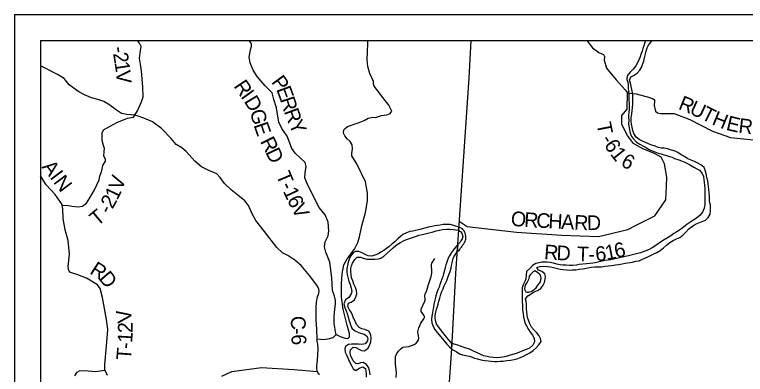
# Model space of a CAD drawing. Extents: x -84548 to 2262448, y -162180 to 525962.
# Drawn here: x -37475 to -22558, y 159669 to 167016 of the extents above; entities that cross this region are included whole.
import ezdxf

# ---------------------------------------------------------------- set-up
doc = ezdxf.new("R2010")
doc.units = 0
for name, color, linetype in [('GM_X_County', 7, 'Continuous'), ('GM_X_County_Road', 7, 'Continuous'), ('GM_X_Interstate_Location', 7, 'Continuous'), ('GM_X_Major_Lake', 7, 'Continuous'), ('GM_X_Minor_Lake', 7, 'Continuous'), ('GM_X_Minor_River_Text', 7, 'Continuous'), ('GM_X_Township_Road', 7, 'Continuous'), ('GM_X_Township_Road_Text', 7, 'Continuous')]:
    doc.layers.add(name, color=color, linetype=linetype)

msp = doc.modelspace()

# ---------------------------------------------------------------- linework, layer by layer
at = {"layer": 'GM_X_County'}
for p, q in [((-37475, 167016), (-515, 167016)), ((-37475, 167016), (-37475, 130056)), ((-36947, 166488), (-36947, 130584)), ((-36947, 166488), (-1043, 166488)), ((-36947, 166488), (-36947, 130584)), ((-36947, 166488), (-1043, 166488))]:
    msp.add_line(p, q, dxfattribs=at)
at = {"layer": 'GM_X_Interstate_Location'}
for p, q in [((-28406, 162678), (-28411, 162615)), ((-28411, 162615), (-28406, 162678)), ((-28430, 162322), (-28440, 162173)), ((-28440, 162173), (-28430, 162322)), ((-28547, 160299), (-28554, 160184)), ((-28554, 160184), (-28547, 160299))]:
    msp.add_line(p, q, dxfattribs=at)
for points in [[(-24599, 166488), (-24619, 166428), (-24633, 166378), (-24651, 166326), (-24665, 166270), (-24683, 166220), (-24706, 166156), (-24728, 166106), (-24758, 166034), (-24794, 165971), (-24846, 165899), (-24914, 165835), (-24973, 165765), (-24979, 165693), (-24957, 165639), (-24953, 165587), (-24951, 165519), (-24945, 165450), (-24937, 165384), (-24934, 165332), (-24934, 165266), (-24932, 165200), (-24932, 165092), (-24940, 165014), (-24946, 164964), (-24944, 164914), (-24939, 164862), (-24941, 164788), (-24937, 164738), (-24923, 164668), (-24907, 164598), (-24883, 164530), (-24845, 164478), (-24779, 164410), (-24712, 164368), (-24640, 164328), (-24578, 164292), (-24522, 164263), (-24464, 164237), (-24408, 164215), (-24340, 164189), (-24278, 164173), (-24218, 164149), (-24166, 164136), (-24108, 164120), (-24054, 164104), (-24002, 164080), (-23918, 164052), (-23860, 164030), (-23796, 164000), (-23742, 163973), (-23676, 163939)], [(-23402, 163897), (-23464, 163947), (-23530, 163983), (-23594, 164013), (-23734, 164073), (-23799, 164115), (-23867, 164154), (-23937, 164202), (-23989, 164224), (-24063, 164250), (-24145, 164276), (-24215, 164288), (-24277, 164289), (-24337, 164299), (-24401, 164327), (-24469, 164351), (-24537, 164379), (-24609, 164411), (-24659, 164432), (-24725, 164468), (-24787, 164516), (-24833, 164586), (-24857, 164648), (-24867, 164716), (-24883, 164780), (-24889, 164848), (-24888, 164910), (-24878, 164990), (-24870, 165048), (-24860, 165118), (-24858, 165178), (-24854, 165235), (-24852, 165289), (-24857, 165357), (-24863, 165425), (-24887, 165545), (-24905, 165613), (-24925, 165679), (-24893, 165745), (-24829, 165781), (-24768, 165817), (-24710, 165882), (-24674, 165950), (-24656, 166000), (-24634, 166068), (-24614, 166130), (-24581, 166266), (-24563, 166336), (-24533, 166394), (-24483, 166461), (-24454, 166488)], [(-23676, 163939), (-23608, 163903), (-23546, 163869), (-23496, 163837), (-23440, 163769), (-23416, 163709), (-23404, 163641), (-23400, 163591), (-23393, 163527), (-23387, 163455), (-23385, 163397), (-23383, 163325), (-23383, 163137), (-23396, 163061), (-23426, 162993), (-23482, 162922), (-23556, 162856), (-23612, 162822), (-23750, 162730), (-23817, 162681), (-23883, 162629), (-23955, 162583), (-24017, 162543), (-24077, 162496), (-24137, 162462), (-24215, 162414), (-24288, 162368), (-24340, 162332), (-24406, 162287), (-24458, 162255), (-24536, 162215), (-24590, 162191), (-24644, 162173), (-24696, 162148), (-24756, 162138), (-24810, 162126), (-24887, 162104), (-24945, 162092), (-25009, 162077), (-25065, 162065), (-25125, 162049), (-25181, 162037), (-25245, 162023), (-25305, 162011), (-25357, 162004), (-25425, 161994), (-25483, 161980), (-25567, 161960), (-25623, 161948), (-25675, 161939), (-25731, 161931), (-25802, 161925), (-25876, 161917), (-25956, 161913), (-26008, 161900), (-26080, 161896), (-26146, 161896), (-26216, 161898), (-26284, 161902), (-26338, 161907), (-26406, 161923), (-26476, 161939), (-26544, 161955), (-26612, 161961), (-26716, 161960), (-26770, 161950), (-26838, 161934), (-26906, 161890), (-26961, 161830), (-27025, 161769), (-27033, 161695), (-27041, 161623), (-27057, 161569), (-27095, 161501), (-27113, 161435), (-27116, 161369), (-27114, 161319), (-27114, 161205), (-27112, 161145), (-27108, 161095), (-27108, 161045), (-27106, 160995), (-27095, 160906), (-27087, 160846), (-27073, 160782), (-27051, 160710), (-27027, 160658), (-26983, 160587), (-26953, 160533), (-26905, 160469), (-26868, 160407), (-26860, 160333), (-26896, 160266), (-26966, 160208), (-27032, 160178), (-27084, 160154), (-27214, 160103), (-27285, 160083), (-27361, 160059), (-27441, 160037), (-27507, 160023)], [(-27147, 160014), (-27089, 160040), (-27026, 160072), (-26956, 160112), (-26890, 160158), (-26826, 160211), (-26772, 160273), (-26728, 160341), (-26739, 160399), (-26765, 160455), (-26817, 160521), (-26867, 160569), (-26921, 160633), (-26959, 160703), (-26979, 160757), (-27003, 160831), (-27011, 160887), (-27020, 160949), (-27024, 160999), (-27024, 161105), (-27034, 161161), (-27044, 161213), (-26996, 161273), (-26932, 161317), (-26869, 161353), (-26801, 161382), (-26735, 161426), (-26683, 161494), (-26659, 161544), (-26643, 161612), (-26639, 161666), (-26653, 161722), (-26716, 161772), (-26784, 161794), (-26818, 161850), (-26754, 161872), (-26678, 161878), (-26600, 161873), (-26534, 161865), (-26472, 161853), (-26340, 161821), (-26276, 161810), (-26212, 161804), (-26154, 161798), (-26098, 161802), (-26020, 161806), (-25950, 161821), (-25892, 161827), (-25840, 161833), (-25776, 161847), (-25704, 161857), (-25636, 161863), (-25566, 161866), (-25495, 161868), (-25427, 161876), (-25357, 161886), (-25291, 161892), (-25211, 161905), (-25141, 161915), (-25071, 161927), (-25015, 161939), (-24863, 161964), (-24793, 161978), (-24725, 161990), (-24671, 162018), (-24597, 162051), (-24546, 162073), (-24438, 162121), (-24364, 162157), (-24296, 162202), (-24232, 162254), (-24168, 162310), (-24101, 162360), (-24029, 162404), (-23967, 162437), (-23899, 162465), (-23831, 162517), (-23771, 162573), (-23715, 162638), (-23640, 162698), (-23578, 162736), (-23508, 162766), (-23442, 162790), (-23372, 162819), (-23316, 162875), (-23280, 162943), (-23268, 163011), (-23267, 163061), (-23273, 163127), (-23289, 163201), (-23291, 163269), (-23293, 163319), (-23299, 163373), (-23301, 163453), (-23308, 163507), (-23316, 163561), (-23326, 163619), (-23342, 163687), (-23356, 163765), (-23376, 163837), (-23402, 163897)], [(-28406, 162678), (-28511, 162710), (-28585, 162731), (-28650, 162733), (-28726, 162729), (-28790, 162719), (-28840, 162711), (-28898, 162701), (-28960, 162689), (-29029, 162673), (-29099, 162653), (-29177, 162635), (-29231, 162623), (-29293, 162607), (-29349, 162597), (-29406, 162585), (-29474, 162561), (-29548, 162525), (-29600, 162487), (-29650, 162439), (-29715, 162373), (-29767, 162333), (-29835, 162277), (-29885, 162237), (-29939, 162199), (-29996, 162163), (-30046, 162133), (-30120, 162101), (-30184, 162085), (-30258, 162091), (-30320, 162117), (-30382, 162151), (-30445, 162177), (-30517, 162179), (-30567, 162149), (-30621, 162085), (-30647, 162025), (-30667, 161959), (-30682, 161893), (-30690, 161829), (-30696, 161764), (-30688, 161712), (-30654, 161576), (-30628, 161502), (-30604, 161432), (-30594, 161362), (-30606, 161312), (-30654, 161240), (-30722, 161192), (-30755, 161109), (-30733, 161035), (-30705, 160969), (-30685, 160911), (-30667, 160845), (-30649, 160785), (-30633, 160729), (-30617, 160679), (-30589, 160611), (-30537, 160568), (-30484, 160538), (-30414, 160512), (-30342, 160488), (-30292, 160458), (-30266, 160408), (-30270, 160352), (-30316, 160290), (-30389, 160278), (-30457, 160284), (-30525, 160286), (-30589, 160286), (-30657, 160278), (-30719, 160242), (-30733, 160192), (-30725, 160124), (-30695, 160056), (-30657, 159972), (-30623, 159901), (-30589, 159835), (-30563, 159783), (-30507, 159749), (-30439, 159797), (-30367, 159823), (-30313, 159791), (-30303, 159735), (-30301, 159681), (-30301, 159611)], [(-30217, 159659), (-30221, 159717), (-30247, 159803), (-30291, 159871), (-30361, 159911), (-30411, 159907), (-30461, 159887), (-30511, 159889), (-30565, 159947), (-30593, 160006), (-30615, 160056), (-30625, 160124), (-30621, 160174), (-30561, 160222), (-30509, 160216), (-30445, 160184), (-30391, 160158), (-30339, 160150), (-30262, 160196), (-30230, 160256), (-30204, 160336), (-30196, 160412), (-30206, 160478), (-30246, 160554), (-30324, 160586), (-30390, 160602), (-30442, 160628), (-30496, 160687), (-30526, 160753), (-30554, 160819), (-30580, 160881), (-30604, 160937), (-30638, 160989), (-30676, 161057), (-30660, 161121), (-30608, 161143), (-30540, 161195), (-30510, 161254), (-30490, 161316), (-30494, 161380), (-30514, 161444), (-30548, 161512), (-30572, 161582), (-30596, 161642), (-30606, 161700), (-30611, 161770), (-30609, 161829), (-30601, 161885), (-30577, 161937), (-30529, 162015), (-30479, 162065), (-30415, 162061), (-30361, 162043), (-30288, 162023), (-30238, 162019), (-30180, 162019), (-30124, 162022), (-30050, 162028), (-30000, 162044), (-29939, 162084), (-29879, 162137), (-29811, 162199), (-29743, 162257), (-29669, 162319), (-29600, 162363), (-29526, 162405), (-29474, 162423), (-29414, 162445), (-29356, 162461), (-29271, 162495), (-29219, 162513), (-29155, 162529), (-29093, 162541), (-29015, 162559), (-28953, 162575), (-28868, 162599), (-28804, 162611), (-28738, 162628), (-28652, 162636), (-28592, 162636), (-28523, 162630), (-28411, 162615)], [(-28440, 162173), (-28389, 162222), (-28371, 162246), (-28355, 162266), (-28340, 162288), (-28322, 162314), (-28304, 162338), (-28290, 162362), (-28278, 162386), (-28270, 162410), (-28266, 162430), (-28264, 162452), (-28264, 162472), (-28266, 162494), (-28270, 162514), (-28273, 162536), (-28279, 162556), (-28291, 162578), (-28301, 162603), (-28323, 162629), (-28339, 162651), (-28406, 162678)], [(-28411, 162615), (-28365, 162577), (-28348, 162555), (-28338, 162531), (-28330, 162498), (-28328, 162478), (-28334, 162458), (-28342, 162436), (-28350, 162416), (-28366, 162394), (-28382, 162372), (-28430, 162322)], [(-28430, 162322), (-28500, 162236), (-28554, 162158), (-28598, 162090), (-28626, 162039), (-28654, 161961), (-28669, 161909), (-28685, 161853), (-28699, 161789), (-28719, 161725), (-28735, 161667), (-28753, 161611), (-28773, 161559), (-28793, 161503), (-28811, 161453), (-28834, 161395), (-28854, 161338), (-28876, 161270), (-28890, 161214), (-28904, 161156), (-28914, 161104), (-28926, 161038), (-28936, 160982), (-28946, 160928), (-28958, 160860), (-28962, 160798), (-28957, 160724), (-28937, 160669), (-28903, 160595), (-28850, 160527), (-28808, 160475), (-28744, 160405), (-28704, 160353), (-28654, 160283), (-28554, 160184)], [(-28547, 160299), (-28649, 160423), (-28758, 160561), (-28816, 160631), (-28860, 160697), (-28886, 160772), (-28892, 160822), (-28892, 160874), (-28878, 160940), (-28862, 161000), (-28840, 161056), (-28826, 161106), (-28814, 161166), (-28796, 161228), (-28782, 161278), (-28761, 161346), (-28729, 161419), (-28703, 161475), (-28679, 161533), (-28653, 161589), (-28629, 161649), (-28601, 161721), (-28581, 161771), (-28566, 161839), (-28556, 161895), (-28546, 161945), (-28528, 162017), (-28512, 162067), (-28440, 162173)], [(-26855, 161786), (-26899, 161758), (-26925, 161730), (-26945, 161708), (-26969, 161675), (-26979, 161637), (-26987, 161607), (-27011, 161555), (-27051, 161493), (-27061, 161457), (-27064, 161409), (-27036, 161353)], [(-27036, 161353), (-27010, 161347), (-26976, 161351), (-26958, 161355), (-26930, 161365), (-26897, 161383), (-26863, 161408), (-26831, 161434), (-26793, 161492), (-26761, 161532), (-26743, 161560), (-26731, 161604), (-26729, 161628), (-26743, 161698), (-26755, 161710), (-26799, 161750), (-26855, 161786)], [(-28317, 160227), (-28426, 160264), (-28547, 160299)], [(-27507, 160023), (-27573, 160016), (-27645, 160010), (-27709, 160012), (-27777, 160024), (-27829, 160032), (-27901, 160049), (-27971, 160079), (-28047, 160119), (-28119, 160153), (-28189, 160181), (-28259, 160207), (-28317, 160227)], [(-28554, 160184), (-28461, 160138)], [(-28461, 160138), (-28391, 160090), (-28329, 160066), (-28267, 160056), (-28199, 160043), (-28135, 160021), (-28085, 160001), (-28025, 159987), (-27957, 159969), (-27879, 159953), (-27807, 159944), (-27739, 159938), (-27677, 159934), (-27625, 159934), (-27561, 159936), (-27501, 159942), (-27427, 159951), (-27355, 159959), (-27275, 159975), (-27223, 159985), (-27147, 160014)]]:
    msp.add_lwpolyline(points, dxfattribs=at)
at = {"layer": 'GM_X_Major_Lake'}
for p, q in [((-28161, 166488), (-28206, 165718)), ((-28206, 165718), (-28474, 161726)), ((-28474, 161726), (-28557, 160201)), ((-28557, 160201), (-28663, 158686))]:
    msp.add_line(p, q, dxfattribs=at)
at = {"layer": 'GM_X_Minor_Lake'}
for points in [[(-35023, 164960), (-34967, 165052), (-34884, 165236), (-34850, 165340), (-34859, 165541), (-34882, 165863), (-34908, 166003), (-34927, 166129), (-34905, 166275), (-34892, 166361), (-34924, 166433), (-34963, 166488)], [(-31298, 160398), (-31160, 160384), (-31050, 160401), (-30974, 160425), (-30912, 160483), (-30920, 160505), (-30950, 160709), (-30953, 160853), (-30939, 160999), (-30922, 161100), (-30926, 161178), (-30946, 161264), (-30987, 161382), (-30991, 161528), (-30996, 161644), (-31043, 161962), (-31121, 162164), (-31148, 162274), (-31136, 162374), (-31076, 162498), (-31061, 162598), (-31073, 162780), (-31134, 162926), (-31261, 163076), (-31383, 163312), (-31510, 163578), (-31553, 163682), (-31545, 163784), (-31523, 163916), (-31544, 163994), (-31745, 164188), (-31815, 164281), (-31914, 164531), (-32018, 164693), (-32081, 164817), (-32132, 165111), (-32182, 165281), (-32217, 165421), (-32359, 165559), (-32522, 165751), (-32605, 165881), (-32665, 166034), (-32688, 166146), (-32658, 166293), (-32642, 166363), (-32640, 166411), (-32663, 166461), (-32687, 166488)], [(-30728, 164687), (-30678, 164733), (-30444, 164811), (-30340, 164852), (-30256, 164900), (-30170, 164920), (-30110, 164916), (-29984, 164954), (-29876, 164971), (-29806, 164993), (-29776, 165047), (-29839, 165167), (-29961, 165325), (-30090, 165495), (-30138, 165553), (-30148, 165603), (-30146, 165649), (-30221, 165811), (-30267, 165959), (-30280, 166089), (-30268, 166265), (-30263, 166411), (-30266, 166488)], [(-25795, 166488), (-25679, 166340), (-25549, 166242), (-25457, 166198), (-25445, 166189), (-25440, 166178), (-25436, 166159), (-25440, 166086), (-25392, 165925), (-25193, 165681), (-25013, 165480), (-24966, 165417), (-24790, 165396), (-24537, 165330), (-24441, 165294), (-24413, 165274), (-24411, 165248), (-24423, 165160), (-24393, 165044), (-24352, 165007), (-24291, 164994), (-24010, 164994), (-23695, 164872), (-23226, 164635), (-22865, 164505), (-22333, 164453)], [(-24169, 163504), (-24169, 163506), (-24162, 163696), (-24208, 163971), (-24280, 164103), (-24416, 164181), (-24667, 164280), (-24842, 164384), (-24966, 164550), (-25083, 164773), (-25079, 164955), (-24970, 165083), (-24966, 165417)], [(-30912, 160483), (-30826, 160443), (-30729, 160410), (-30675, 160404), (-30641, 160438), (-30638, 160502), (-30684, 160674), (-30769, 161004), (-30804, 161248), (-30805, 161520), (-30788, 161720), (-30752, 161908), (-30685, 162031), (-30539, 162223), (-30470, 162364), (-30432, 162476), (-30387, 162702), (-30314, 162976), (-30274, 163211), (-30269, 163373), (-30314, 163603), (-30479, 163955), (-30594, 164134), (-30594, 164178), (-30580, 164277), (-30584, 164355), (-30623, 164427), (-30687, 164482), (-30737, 164538), (-30761, 164592), (-30755, 164662), (-30735, 164681), (-30728, 164687)], [(-36501, 163120), (-36406, 163127), (-36302, 163105), (-36174, 163092), (-36086, 163106), (-36004, 163164), (-35940, 163272), (-35843, 163441), (-35751, 163639), (-35733, 163717), (-35706, 163791), (-35684, 163863), (-35674, 163933), (-35622, 164022), (-35618, 164062), (-35653, 164122), (-35647, 164220), (-35639, 164284), (-35661, 164344), (-35690, 164442), (-35686, 164547), (-35686, 164548)], [(-36375, 161822), (-36382, 161870), (-36357, 162121), (-36379, 162403), (-36442, 162621), (-36481, 162855), (-36492, 163051), (-36501, 163120), (-36507, 163136), (-36645, 163341), (-36831, 163542), (-36947, 163723)], [(-28402, 162796), (-28235, 162692), (-27229, 162572), (-26304, 162514), (-25554, 162485), (-24955, 162631), (-24877, 162670)], [(-35634, 159757), (-35634, 159868), (-35596, 160251), (-35575, 160584), (-35602, 160790), (-35681, 161236), (-35728, 161424), (-35786, 161498), (-36009, 161631), (-36187, 161705), (-36331, 161748), (-36371, 161790), (-36373, 161801), (-36375, 161822)], [(-33242, 159633), (-33041, 159731), (-32434, 159811), (-31774, 159766), (-31295, 159728)], [(-36248, 159637), (-36198, 159712), (-36147, 159744), (-36046, 159746), (-35824, 159730), (-35634, 159757), (-35586, 159655)]]:
    msp.add_lwpolyline(points, dxfattribs=at)
at = {"layer": 'GM_X_Minor_River_Text'}
msp.add_lwpolyline([(-31243, 159664), (-31262, 159676), (-31278, 159691), (-31288, 159709), (-31295, 159728), (-31303, 159780), (-31303, 159853), (-31294, 159954), (-31279, 160182), (-31287, 160284), (-31298, 160344), (-31298, 160398), (-31308, 160596), (-31317, 160774), (-31321, 160910), (-31322, 161026), (-31310, 161145), (-31289, 161255), (-31265, 161325), (-31260, 161373), (-31265, 161409), (-31287, 161459), (-31307, 161489), (-31454, 161691), (-31623, 161890), (-31757, 162002), (-31898, 162094), (-32006, 162152), (-32120, 162261), (-32376, 162585), (-32554, 162813), (-32635, 162962), (-32702, 163116), (-32772, 163216), (-32916, 163328), (-33055, 163440), (-33187, 163567), (-33280, 163687), (-33350, 163765), (-33526, 163837), (-33661, 163908), (-33799, 164020), (-33974, 164222), (-34062, 164294), (-34177, 164365), (-34277, 164483), (-34478, 164689), (-34662, 164825), (-34837, 164904), (-34953, 164944), (-35023, 164960), (-35183, 164979), (-35291, 164995), (-35394, 165061), (-35552, 165179), (-35656, 165238), (-35773, 165282), (-35907, 165318), (-36049, 165377), (-36167, 165441), (-36362, 165585), (-36466, 165711), (-36599, 165792), (-36849, 165922), (-36947, 165973)], dxfattribs=at)
at = {"layer": 'GM_X_Township_Road_Text'}
for points in [[(-35686, 164548), (-35684, 164604), (-35660, 164662), (-35385, 164811), (-35173, 164899), (-35051, 164924), (-35023, 164960)], [(-24877, 162670), (-24869, 162674), (-24408, 162904), (-24179, 163231), (-24169, 163504)], [(-29689, 159604), (-29680, 159700), (-29698, 159884), (-29698, 159971), (-29698, 160033), (-29673, 160093), (-29638, 160143), (-29594, 160193), (-29549, 160225), (-29427, 160242), (-29322, 160277), (-29280, 160304), (-29252, 160339), (-29232, 160378), (-29226, 160417), (-29243, 160540), (-29226, 160618), (-29182, 160715), (-29121, 160802), (-29115, 160816), (-29111, 160832), (-29110, 160850), (-29114, 160865), (-29122, 160878), (-29173, 160951), (-29177, 160981), (-29173, 161003), (-29104, 161163), (-29096, 161187), (-29093, 161210), (-29102, 161269), (-29100, 161290), (-29094, 161312), (-29068, 161362), (-29025, 161502), (-28972, 161668), (-28960, 161736), (-28955, 161799), (-28967, 161870), (-28967, 161912), (-28957, 161938), (-28894, 162035)]]:
    msp.add_lwpolyline(points, dxfattribs=at)

# ---------------------------------------------------------------- texts
at = {"layer": 'GM_X_County_Road'}
for s, rotation, p in [('C', 271.413, (-31837, 160861)), ('-', 272.3411, (-31831, 160609)), ('6', 272.8938, (-31826, 160483))]:
    msp.add_text(s, height=300, rotation=rotation, dxfattribs=at).set_placement(p)
at = {"layer": 'GM_X_Township_Road'}
for s, rotation, p in [('-', 278.9539, (-35485, 166345)), ('2', 279.0366, (-35466, 166223)), ('1', 278.5135, (-35437, 166041)), ('V', 275.9484, (-35410, 165862)), ('P', 306.2475, (-32246, 165637)), ('R', 303.846, (-33013, 165556)), ('I', 305.7675, (-32870, 165342)), ('E', 290.2065, (-32137, 165493)), ('D', 301.0562, (-32801, 165248)), ('R', 287.9413, (-32061, 165286)), ('R', 338.1232, (-23943, 165092)), ('U', 335.0569, (-23718, 165002)), ('T', 333.3621, (-23481, 164892)), ('G', 284.4171, (-32674, 165043)), ('R', 290.3083, (-31980, 165039)), ('H', 337.7328, (-23258, 164781)), ('Y', 294.2716, (-31886, 164787)), ('T', 281.2515, (-25599, 164790)), ('E', 346.2408, (-22967, 164666)), ('R', 353.2962, (-22710, 164605)), ('E', 289.1637, (-32600, 164761)), ('R', 296.5234, (-32469, 164428)), ('-', 300.7817, (-25516, 164466)), ('6', 301.6939, (-25450, 164356)), ('D', 295.5191, (-32360, 164208)), ('1', 308.5718, (-25330, 164166)), ('6', 330.54, (-25120, 163941)), ('A', 307.7529, (-36928, 163902)), ('I', 306.948, (-36767, 163694)), ('T', 292.9634, (-32144, 163740)), ('N', 306.9391, (-36693, 163596)), ('V', 70.4916, (-35285, 163411)), ('-', 293.7212, (-32054, 163530)), ('1', 64.3989, (-35378, 163212)), ('1', 294.9379, (-32002, 163411)), ('2', 60.9044, (-35477, 163033)), ('6', 296.3977, (-31920, 163236)), ('V', 297.472, (-31835, 163065)), ('T', 39.9021, (-35786, 162682)), ('-', 62.5275, (-35533, 162926)), ('O', 354.2127, (-27357, 162709)), ('R', 356.8899, (-27079, 162681)), ('C', 356.9726, (-26832, 162668)), ('H', 356.9714, (-26586, 162655)), ('A', 356.9751, (-26323, 162641)), ('R', 357.0262, (-26059, 162627)), ('D', 0.8711, (-25791, 162614)), ('R', 355.5657, (-26674, 162025)), ('D', 357.3654, (-26419, 162005)), ('6', 5.8579, (-25606, 161976)), ('1', 11.2167, (-25392, 162000)), ('6', 13.8962, (-25196, 162039)), ('T', 357.8195, (-26000, 161982)), ('-', 0.499, (-25760, 161973)), ('R', 327.4022, (-35960, 161739)), ('D', 310.1335, (-35771, 161622)), ('V', 98.8912, (-35070, 160747)), ('2', 90.6345, (-35064, 160515)), ('1', 86.7223, (-35075, 160308)), ('T', 85.7535, (-35101, 159956)), ('-', 85.9377, (-35084, 160181))]:
    msp.add_text(s, height=300, rotation=rotation, dxfattribs=at).set_placement(p)

doc.saveas('drawing.dxf')
